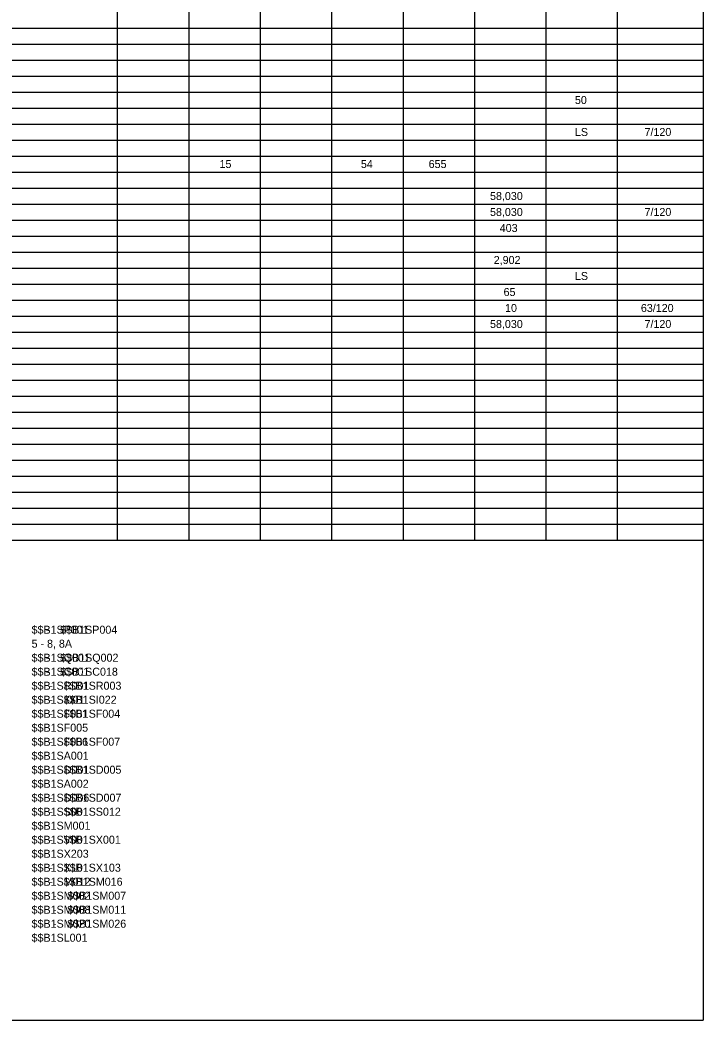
# Model space of a CAD drawing. Extents: x 100 to 128, y 64.8 to 100.
# Drawn here: x 116.05 to 128, y 64.8 to 82.3 of the extents above; entities that cross this region are included whole.
import ezdxf

# ---------------------------------------------------------------- set-up
doc = ezdxf.new("R2010")
doc.units = 0
doc.layers.add('SC_Scratch1', color=7, linetype='Continuous')
doc.layers.add('SH_Text', color=7, linetype='Continuous')

msp = doc.modelspace()

# ---------------------------------------------------------------- linework, layer by layer
at = {"layer": 'SC_Scratch1'}
for p in [(128, 73.2), (100, 64.8)]:
    msp.add_line(p, (128, 64.8), dxfattribs=at)
at = {"layer": 'SH_Text'}
for p, q in [((117.75, 82.44), (117.75, 82.16)), ((119, 82.44), (119, 82.16)), ((120.25, 82.44), (120.25, 82.16)), ((121.5, 82.44), (121.5, 82.16)), ((122.75, 82.44), (122.75, 82.16)), ((124, 82.44), (124, 82.16)), ((125.25, 82.44), (125.25, 82.16)), ((126.5, 82.44), (126.5, 82.16)), ((128, 82.44), (128, 82.16)), ((100, 82.16), (128, 82.16)), ((117.75, 82.16), (117.75, 81.88)), ((119, 82.16), (119, 81.88)), ((120.25, 82.16), (120.25, 81.88)), ((121.5, 82.16), (121.5, 81.88)), ((122.75, 82.16), (122.75, 81.88)), ((124, 82.16), (124, 81.88)), ((125.25, 82.16), (125.25, 81.88)), ((126.5, 82.16), (126.5, 81.88)), ((128, 82.16), (128, 81.88)), ((100, 81.88), (128, 81.88)), ((117.75, 81.88), (117.75, 81.6)), ((119, 81.88), (119, 81.6)), ((120.25, 81.88), (120.25, 81.6)), ((121.5, 81.88), (121.5, 81.6)), ((122.75, 81.88), (122.75, 81.6)), ((124, 81.88), (124, 81.6)), ((125.25, 81.88), (125.25, 81.6)), ((126.5, 81.88), (126.5, 81.6)), ((128, 81.88), (128, 81.6)), ((100, 81.6), (128, 81.6)), ((117.75, 81.6), (117.75, 81.32)), ((119, 81.6), (119, 81.32)), ((120.25, 81.6), (120.25, 81.32)), ((121.5, 81.6), (121.5, 81.32)), ((122.75, 81.6), (122.75, 81.32)), ((124, 81.6), (124, 81.32)), ((125.25, 81.6), (125.25, 81.32)), ((126.5, 81.6), (126.5, 81.32)), ((128, 81.6), (128, 81.32)), ((100, 81.32), (128, 81.32)), ((117.75, 81.32), (117.75, 81.04)), ((119, 81.32), (119, 81.04)), ((120.25, 81.32), (120.25, 81.04)), ((121.5, 81.32), (121.5, 81.04)), ((122.75, 81.32), (122.75, 81.04)), ((124, 81.32), (124, 81.04)), ((125.25, 81.32), (125.25, 81.04)), ((126.5, 81.32), (126.5, 81.04)), ((128, 81.32), (128, 81.04)), ((100, 81.04), (128, 81.04)), ((117.75, 81.04), (117.75, 80.76)), ((119, 81.04), (119, 80.76)), ((120.25, 81.04), (120.25, 80.76)), ((121.5, 81.04), (121.5, 80.76)), ((122.75, 81.04), (122.75, 80.76)), ((124, 81.04), (124, 80.76)), ((125.25, 81.04), (125.25, 80.76)), ((126.5, 81.04), (126.5, 80.76)), ((128, 81.04), (128, 80.76)), ((100, 80.76), (128, 80.76)), ((117.75, 80.76), (117.75, 80.48)), ((119, 80.76), (119, 80.48)), ((120.25, 80.76), (120.25, 80.48)), ((121.5, 80.76), (121.5, 80.48)), ((122.75, 80.76), (122.75, 80.48)), ((124, 80.76), (124, 80.48)), ((125.25, 80.76), (125.25, 80.48)), ((126.5, 80.76), (126.5, 80.48)), ((128, 80.76), (128, 80.48)), ((100, 80.48), (128, 80.48)), ((117.75, 80.48), (117.75, 80.2)), ((119, 80.48), (119, 80.2)), ((120.25, 80.48), (120.25, 80.2)), ((121.5, 80.48), (121.5, 80.2)), ((122.75, 80.48), (122.75, 80.2)), ((124, 80.48), (124, 80.2)), ((125.25, 80.48), (125.25, 80.2)), ((126.5, 80.48), (126.5, 80.2)), ((128, 80.48), (128, 80.2)), ((100, 80.2), (128, 80.2)), ((117.75, 80.2), (117.75, 79.92)), ((119, 80.2), (119, 79.92)), ((120.25, 80.2), (120.25, 79.92)), ((121.5, 80.2), (121.5, 79.92)), ((122.75, 80.2), (122.75, 79.92)), ((124, 80.2), (124, 79.92)), ((125.25, 80.2), (125.25, 79.92)), ((126.5, 80.2), (126.5, 79.92)), ((128, 80.2), (128, 79.92)), ((100, 79.92), (128, 79.92)), ((117.75, 79.92), (117.75, 79.64)), ((119, 79.92), (119, 79.64)), ((120.25, 79.92), (120.25, 79.64)), ((121.5, 79.92), (121.5, 79.64)), ((122.75, 79.92), (122.75, 79.64)), ((124, 79.92), (124, 79.64)), ((125.25, 79.92), (125.25, 79.64)), ((126.5, 79.92), (126.5, 79.64)), ((128, 79.92), (128, 79.64)), ((100, 79.64), (128, 79.64)), ((117.75, 79.64), (117.75, 79.36)), ((119, 79.64), (119, 79.36)), ((120.25, 79.64), (120.25, 79.36)), ((121.5, 79.64), (121.5, 79.36)), ((122.75, 79.64), (122.75, 79.36)), ((124, 79.64), (124, 79.36)), ((125.25, 79.64), (125.25, 79.36)), ((126.5, 79.64), (126.5, 79.36)), ((128, 79.64), (128, 79.36)), ((100, 79.36), (128, 79.36)), ((117.75, 79.36), (117.75, 79.08)), ((119, 79.36), (119, 79.08)), ((120.25, 79.36), (120.25, 79.08)), ((121.5, 79.36), (121.5, 79.08)), ((122.75, 79.36), (122.75, 79.08)), ((124, 79.36), (124, 79.08)), ((125.25, 79.36), (125.25, 79.08)), ((126.5, 79.36), (126.5, 79.08)), ((128, 79.36), (128, 79.08)), ((100, 79.08), (128, 79.08)), ((117.75, 79.08), (117.75, 78.8)), ((119, 79.08), (119, 78.8)), ((120.25, 79.08), (120.25, 78.8)), ((121.5, 79.08), (121.5, 78.8)), ((122.75, 79.08), (122.75, 78.8)), ((124, 79.08), (124, 78.8)), ((125.25, 79.08), (125.25, 78.8)), ((126.5, 79.08), (126.5, 78.8)), ((128, 79.08), (128, 78.8)), ((100, 78.8), (128, 78.8)), ((117.75, 78.8), (117.75, 78.52)), ((119, 78.8), (119, 78.52)), ((120.25, 78.8), (120.25, 78.52)), ((121.5, 78.8), (121.5, 78.52)), ((122.75, 78.8), (122.75, 78.52)), ((124, 78.8), (124, 78.52)), ((125.25, 78.8), (125.25, 78.52)), ((126.5, 78.8), (126.5, 78.52)), ((128, 78.8), (128, 78.52)), ((100, 78.52), (128, 78.52)), ((117.75, 78.52), (117.75, 78.24)), ((119, 78.52), (119, 78.24)), ((120.25, 78.52), (120.25, 78.24)), ((121.5, 78.52), (121.5, 78.24)), ((122.75, 78.52), (122.75, 78.24)), ((124, 78.52), (124, 78.24)), ((125.25, 78.52), (125.25, 78.24)), ((126.5, 78.52), (126.5, 78.24)), ((128, 78.52), (128, 78.24)), ((100, 78.24), (128, 78.24)), ((117.75, 78.24), (117.75, 77.96)), ((119, 78.24), (119, 77.96)), ((120.25, 78.24), (120.25, 77.96)), ((121.5, 78.24), (121.5, 77.96)), ((122.75, 78.24), (122.75, 77.96)), ((124, 78.24), (124, 77.96)), ((125.25, 78.24), (125.25, 77.96)), ((126.5, 78.24), (126.5, 77.96)), ((128, 78.24), (128, 77.96)), ((100, 77.96), (128, 77.96)), ((117.75, 77.96), (117.75, 77.68)), ((119, 77.96), (119, 77.68)), ((120.25, 77.96), (120.25, 77.68)), ((121.5, 77.96), (121.5, 77.68)), ((122.75, 77.96), (122.75, 77.68)), ((124, 77.96), (124, 77.68)), ((125.25, 77.96), (125.25, 77.68)), ((126.5, 77.96), (126.5, 77.68)), ((128, 77.96), (128, 77.68)), ((100, 77.68), (128, 77.68)), ((117.75, 77.68), (117.75, 77.4)), ((119, 77.68), (119, 77.4)), ((120.25, 77.68), (120.25, 77.4)), ((121.5, 77.68), (121.5, 77.4)), ((122.75, 77.68), (122.75, 77.4)), ((124, 77.68), (124, 77.4)), ((125.25, 77.68), (125.25, 77.4)), ((126.5, 77.68), (126.5, 77.4)), ((128, 77.68), (128, 77.4)), ((100, 77.4), (128, 77.4)), ((117.75, 77.4), (117.75, 77.12)), ((119, 77.4), (119, 77.12)), ((120.25, 77.4), (120.25, 77.12)), ((121.5, 77.4), (121.5, 77.12)), ((122.75, 77.4), (122.75, 77.12)), ((124, 77.4), (124, 77.12)), ((125.25, 77.4), (125.25, 77.12)), ((126.5, 77.4), (126.5, 77.12)), ((128, 77.4), (128, 77.12)), ((100, 77.12), (128, 77.12)), ((117.75, 77.12), (117.75, 76.84)), ((119, 77.12), (119, 76.84)), ((120.25, 77.12), (120.25, 76.84)), ((121.5, 77.12), (121.5, 76.84)), ((122.75, 77.12), (122.75, 76.84)), ((124, 77.12), (124, 76.84)), ((125.25, 77.12), (125.25, 76.84)), ((126.5, 77.12), (126.5, 76.84)), ((128, 77.12), (128, 76.84)), ((100, 76.84), (128, 76.84)), ((117.75, 76.84), (117.75, 76.56)), ((119, 76.84), (119, 76.56)), ((120.25, 76.84), (120.25, 76.56)), ((121.5, 76.84), (121.5, 76.56)), ((122.75, 76.84), (122.75, 76.56)), ((124, 76.84), (124, 76.56)), ((125.25, 76.84), (125.25, 76.56)), ((126.5, 76.84), (126.5, 76.56)), ((128, 76.84), (128, 76.56)), ((100, 76.56), (128, 76.56)), ((117.75, 76.56), (117.75, 76.28)), ((119, 76.56), (119, 76.28)), ((120.25, 76.56), (120.25, 76.28)), ((121.5, 76.56), (121.5, 76.28)), ((122.75, 76.56), (122.75, 76.28)), ((124, 76.56), (124, 76.28)), ((125.25, 76.56), (125.25, 76.28)), ((126.5, 76.56), (126.5, 76.28)), ((128, 76.56), (128, 76.28)), ((100, 76.28), (128, 76.28)), ((117.75, 76.28), (117.75, 76)), ((119, 76.28), (119, 76)), ((120.25, 76.28), (120.25, 76)), ((121.5, 76.28), (121.5, 76)), ((122.75, 76.28), (122.75, 76)), ((124, 76.28), (124, 76)), ((125.25, 76.28), (125.25, 76)), ((126.5, 76.28), (126.5, 76)), ((128, 76.28), (128, 76)), ((100, 76), (128, 76)), ((117.75, 76), (117.75, 75.72)), ((119, 76), (119, 75.72)), ((120.25, 76), (120.25, 75.72)), ((121.5, 76), (121.5, 75.72)), ((122.75, 76), (122.75, 75.72)), ((124, 76), (124, 75.72)), ((125.25, 76), (125.25, 75.72)), ((126.5, 76), (126.5, 75.72)), ((128, 76), (128, 75.72)), ((100, 75.72), (128, 75.72)), ((117.75, 75.72), (117.75, 75.44)), ((119, 75.72), (119, 75.44)), ((120.25, 75.72), (120.25, 75.44)), ((121.5, 75.72), (121.5, 75.44)), ((122.75, 75.72), (122.75, 75.44)), ((124, 75.72), (124, 75.44)), ((125.25, 75.72), (125.25, 75.44)), ((126.5, 75.72), (126.5, 75.44)), ((128, 75.72), (128, 75.44)), ((100, 75.44), (128, 75.44)), ((117.75, 75.44), (117.75, 75.16)), ((119, 75.44), (119, 75.16)), ((120.25, 75.44), (120.25, 75.16)), ((121.5, 75.44), (121.5, 75.16)), ((122.75, 75.44), (122.75, 75.16)), ((124, 75.44), (124, 75.16)), ((125.25, 75.44), (125.25, 75.16)), ((126.5, 75.44), (126.5, 75.16)), ((128, 75.44), (128, 75.16)), ((100, 75.16), (128, 75.16)), ((117.75, 75.16), (117.75, 74.88)), ((119, 75.16), (119, 74.88)), ((120.25, 75.16), (120.25, 74.88)), ((121.5, 75.16), (121.5, 74.88)), ((122.75, 75.16), (122.75, 74.88)), ((124, 75.16), (124, 74.88)), ((125.25, 75.16), (125.25, 74.88)), ((126.5, 75.16), (126.5, 74.88)), ((128, 75.16), (128, 74.88)), ((100, 74.88), (128, 74.88)), ((117.75, 74.88), (117.75, 74.6)), ((119, 74.88), (119, 74.6)), ((120.25, 74.88), (120.25, 74.6)), ((121.5, 74.88), (121.5, 74.6)), ((122.75, 74.88), (122.75, 74.6)), ((124, 74.88), (124, 74.6)), ((125.25, 74.88), (125.25, 74.6)), ((126.5, 74.88), (126.5, 74.6)), ((128, 74.88), (128, 74.6)), ((100, 74.6), (128, 74.6)), ((117.75, 74.6), (117.75, 74.32)), ((119, 74.6), (119, 74.32)), ((120.25, 74.6), (120.25, 74.32)), ((121.5, 74.6), (121.5, 74.32)), ((122.75, 74.6), (122.75, 74.32)), ((124, 74.6), (124, 74.32)), ((125.25, 74.6), (125.25, 74.32)), ((126.5, 74.6), (126.5, 74.32)), ((128, 74.6), (128, 74.32)), ((100, 74.32), (128, 74.32)), ((117.75, 74.32), (117.75, 74.04)), ((119, 74.32), (119, 74.04)), ((120.25, 74.32), (120.25, 74.04)), ((121.5, 74.32), (121.5, 74.04)), ((122.75, 74.32), (122.75, 74.04)), ((124, 74.32), (124, 74.04)), ((125.25, 74.32), (125.25, 74.04)), ((126.5, 74.32), (126.5, 74.04)), ((128, 74.32), (128, 74.04)), ((100, 74.04), (128, 74.04)), ((117.75, 74.04), (117.75, 73.76)), ((119, 74.04), (119, 73.76)), ((120.25, 74.04), (120.25, 73.76)), ((121.5, 74.04), (121.5, 73.76)), ((122.75, 74.04), (122.75, 73.76)), ((124, 74.04), (124, 73.76)), ((125.25, 74.04), (125.25, 73.76)), ((126.5, 74.04), (126.5, 73.76)), ((128, 74.04), (128, 73.76)), ((100, 73.76), (128, 73.76)), ((117.75, 73.76), (117.75, 73.48)), ((119, 73.76), (119, 73.48)), ((120.25, 73.76), (120.25, 73.48)), ((121.5, 73.76), (121.5, 73.48)), ((122.75, 73.76), (122.75, 73.48)), ((124, 73.76), (124, 73.48)), ((125.25, 73.76), (125.25, 73.48)), ((126.5, 73.76), (126.5, 73.48)), ((128, 73.76), (128, 73.48)), ((100, 73.48), (128, 73.48)), ((117.75, 73.48), (117.75, 73.2)), ((119, 73.48), (119, 73.2)), ((120.25, 73.48), (120.25, 73.2)), ((121.5, 73.48), (121.5, 73.2)), ((122.75, 73.48), (122.75, 73.2)), ((124, 73.48), (124, 73.2)), ((125.25, 73.48), (125.25, 73.2)), ((126.5, 73.48), (126.5, 73.2)), ((128, 73.48), (128, 73.2)), ((100, 73.2), (128, 73.2))]:
    msp.add_line(p, q, dxfattribs=at)

# ---------------------------------------------------------------- texts
for s, p in [('50', (125.759, 80.83)), ('LS', (125.759, 80.27)), ('7/120', (126.977, 80.27)), ('15', (119.539, 79.71)), ('54', (122.013, 79.71)), ('655', (123.199, 79.71)), ('58,030', (124.273, 79.15)), ('58,030', (124.273, 78.87)), ('7/120', (126.977, 78.87)), ('403', (124.443, 78.59)), ('2,902', (124.338, 78.03)), ('LS', (125.759, 77.75)), ('65', (124.51, 77.47)), ('10', (124.536, 77.19)), ('63/120', (126.913, 77.19)), ('58,030', (124.273, 76.91)), ('7/120', (126.977, 76.91)), ('$$B1SP001', (116.25, 71.56)), ('-', (116.5, 71.56)), ('$$B1SP004', (116.75, 71.56)), ('5 - 8, 8A', (116.25, 71.315)), ('$$B1SQ001', (116.25, 71.07)), ('-', (116.5, 71.07)), ('$$B1SQ002', (116.75, 71.07)), ('$$B1SC001', (116.25, 70.825)), ('-', (116.5, 70.825)), ('$$B1SC018', (116.75, 70.825)), ('$$B1SR001', (116.25, 70.58)), ('$$B1SR003', (116.812, 70.58)), ('-', (116.562, 70.58)), ('$$B1SI001', (116.25, 70.335)), ('-', (116.562, 70.335)), ('$$B1SI022', (116.812, 70.335)), ('$$B1SF001', (116.25, 70.09)), ('$$B1SF004', (116.812, 70.09)), ('-', (116.562, 70.09)), ('$$B1SF005', (116.25, 69.845)), ('$$B1SF006', (116.25, 69.6)), ('-', (116.562, 69.6)), ('$$B1SF007', (116.812, 69.6)), ('$$B1SA001', (116.25, 69.355)), ('$$B1SD001', (116.25, 69.11)), ('-', (116.562, 69.11)), ('$$B1SD005', (116.812, 69.11)), ('$$B1SA002', (116.25, 68.865)), ('$$B1SD006', (116.25, 68.62)), ('-', (116.562, 68.62)), ('$$B1SD007', (116.812, 68.62)), ('$$B1SS001', (116.25, 68.375)), ('-', (116.562, 68.375)), ('$$B1SS012', (116.812, 68.375)), ('$$B1SM001', (116.25, 68.13)), ('$$B1SV001', (116.25, 67.885)), ('-', (116.562, 67.885)), ('$$B1SX001', (116.812, 67.885)), ('$$B1SX203', (116.25, 67.64)), ('$$B1SX101', (116.25, 67.395)), ('-', (116.562, 67.395)), ('$$B1SX103', (116.812, 67.395)), ('$$B1SM012', (116.25, 67.15)), ('-', (116.562, 67.15)), ('$$B1SM016', (116.812, 67.15)), ('$$B1SM002', (116.25, 66.905)), ('$$B1SM007', (116.875, 66.905)), ('-', (116.625, 66.905)), ('$$B1SM008', (116.25, 66.66)), ('-', (116.625, 66.66)), ('$$B1SM011', (116.875, 66.66)), ('$$B1SM020', (116.25, 66.415)), ('$$B1SM026', (116.875, 66.415)), ('-', (116.625, 66.415)), ('$$B1SL001', (116.25, 66.17))]:
    msp.add_text(s, height=0.14, dxfattribs=at).set_placement(p)

doc.saveas('drawing.dxf')
